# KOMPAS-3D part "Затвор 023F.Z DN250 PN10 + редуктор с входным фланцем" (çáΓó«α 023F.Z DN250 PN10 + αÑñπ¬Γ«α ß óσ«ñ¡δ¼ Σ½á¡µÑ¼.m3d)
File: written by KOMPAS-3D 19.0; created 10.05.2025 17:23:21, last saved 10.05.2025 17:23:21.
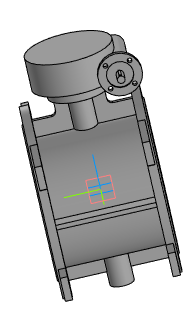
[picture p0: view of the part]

Document properties: Полное имя файла: Затвор 023F.Z DN250 PN10 + редуктор с входным фланцем.a3d

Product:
- Part/product: Затвор 023F.Z DN250 PN10 + редуктор с входным фланцем
    Масса: 75.43

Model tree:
1. Операция без истории:1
